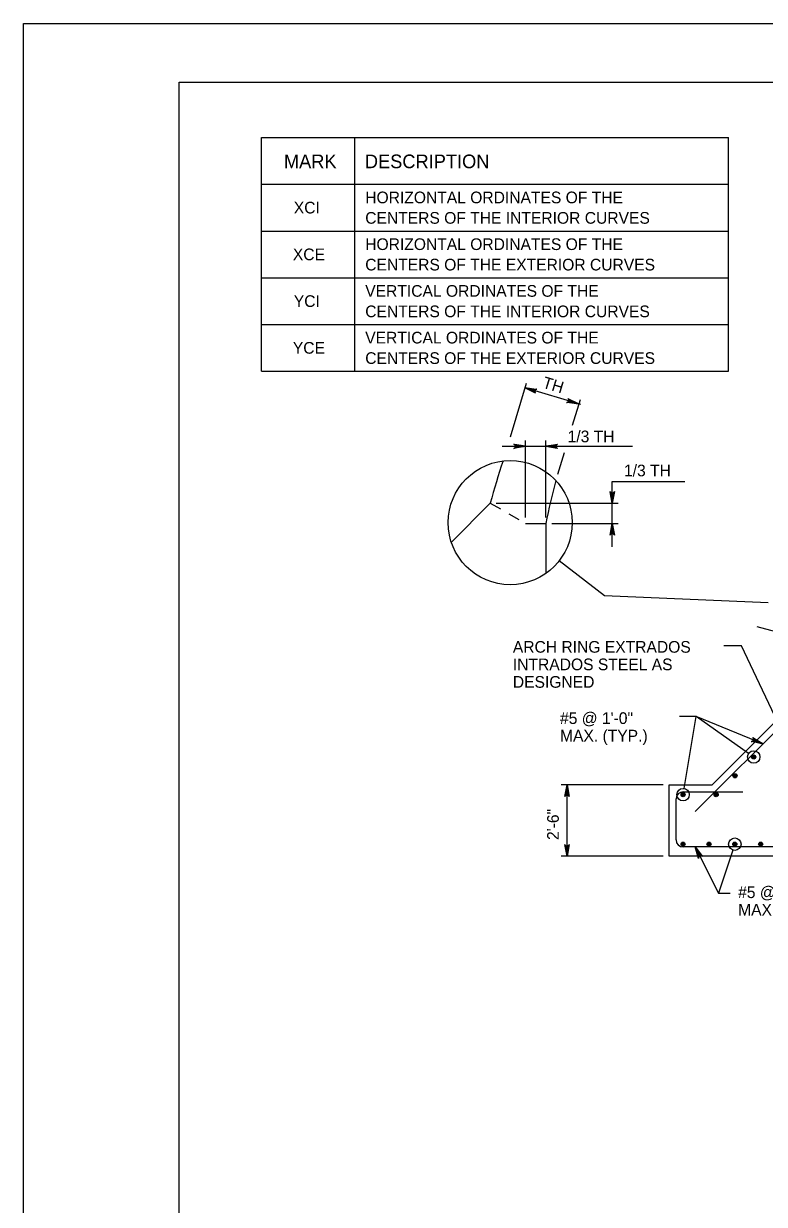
# Model space of a CAD drawing. Extents: x 639028 to 639883, y 298843 to 300031.
# Drawn here: x 639027.7 to 639218, y 299727.9 to 300031.1 of the extents above; entities that cross this region are included whole.
import ezdxf

# ---------------------------------------------------------------- set-up
doc = ezdxf.new("R2010")
doc.units = 0
for name, color, linetype in [('1', 7, 'Continuous'), ('2', 7, 'Continuous'), ('52', 7, 'Continuous'), ('PLT-BNDY', 7, 'Continuous')]:
    doc.layers.add(name, color=color, linetype=linetype)

# ---------------------------------------------------------------- blocks, each defined once
blk = doc.blocks.new('LT')
at = {"layer": '1'}
blk.add_lwpolyline([(0, 0), (-11.2, -2.1), (-10.8, -1.8), (-10.3, -1.5), (-10.1, -1.1), (-9.9, -0.8), (-9.8, -0.4), (-9.8, 0), (-9.8, 0.4), (-9.9, 0.8), (-10.1, 1.1), (-10.3, 1.5), (-10.8, 1.8), (-11.2, 2.1), (0, 0), (-10.8, 1.8), (-10.3, 1.5), (0, 0), (-10.1, 1.1), (-9.9, 0.8), (0, 0), (-9.8, 0.4), (-9.8, 0), (0, 0), (-9.8, -0.4), (-9.9, -0.8), (0, 0), (-10.1, -1.1), (-10.3, -1.5), (0, 0), (-10.8, -1.8)], dxfattribs=at)

msp = doc.modelspace()

# ---------------------------------------------------------------- linework, layer by layer
at = {"layer": '2'}
for p, q in [((639067.74, 299452.08), (639067.74, 300016.08)), ((639067.74, 300016.08), (639853.74, 300016.08)), ((639088.81, 299941.83), (639088.81, 300001.83)), ((639088.81, 300001.83), (639208.81, 300001.83)), ((639112.81, 299941.83), (639112.81, 300001.83)), ((639208.81, 299941.83), (639208.81, 300001.83)), ((639088.81, 299989.83), (639208.81, 299989.83)), ((639088.81, 299977.83), (639208.81, 299977.83)), ((639088.81, 299965.83), (639208.81, 299965.83)), ((639088.81, 299953.83), (639208.81, 299953.83)), ((639088.81, 299941.83), (639208.81, 299941.83)), ((639137.62, 299897.94), (639147.63, 299907.95)), ((639147.63, 299907.95), (639150.24, 299906.46)), ((639152.43, 299905.2), (639154.98, 299903.75)), ((639156.71, 299902.76), (639161.9, 299902.76)), ((639161.9, 299902.76), (639161.9, 299889.92)), ((639204.59, 299835.65), (639239.04, 299870.11)), ((639200.24, 299828.76), (639238.07, 299866.59)), ((639193.55, 299817.28), (639193.55, 299835.65)), ((639193.55, 299835.65), (639204.59, 299835.65)), ((639195.35, 299821.48), (639195.35, 299832.05)), ((639197.15, 299833.85), (639212.53, 299833.85)), ((639256.92, 299819.68), (639197.15, 299819.68)), ((639260.52, 299817.28), (639193.55, 299817.28))]:
    msp.add_line(p, q, dxfattribs=at)
for centre, radius in [((639215.3, 299842.8), 0.533), ((639215.3, 299842.8), 0.4), ((639215.3, 299842.8), 0.267), ((639215.3, 299842.8), 0.133), ((639210.47, 299837.96), 0.533), ((639210.47, 299837.96), 0.4), ((639210.47, 299837.96), 0.267), ((639210.47, 299837.96), 0.133), ((639197.15, 299833.13), 0.533), ((639197.15, 299833.13), 0.4), ((639197.15, 299833.13), 0.267), ((639197.15, 299833.13), 0.133), ((639205.63, 299833.13), 0.533), ((639205.63, 299833.13), 0.4), ((639205.63, 299833.13), 0.267), ((639205.63, 299833.13), 0.133), ((639197.15, 299820.4), 0.533), ((639197.15, 299820.4), 0.4), ((639197.15, 299820.4), 0.267), ((639197.15, 299820.4), 0.133), ((639203.79, 299820.4), 0.533), ((639203.79, 299820.4), 0.4), ((639203.79, 299820.4), 0.267), ((639203.79, 299820.4), 0.133), ((639210.43, 299820.4), 0.533), ((639210.43, 299820.4), 0.4), ((639210.43, 299820.4), 0.267), ((639210.43, 299820.4), 0.133), ((639217.07, 299820.4), 0.533), ((639217.07, 299820.4), 0.4), ((639217.07, 299820.4), 0.267), ((639217.07, 299820.4), 0.133)]:
    msp.add_circle(centre, radius, dxfattribs=at)
for centre, radius, start, end in [((639312.8, 299863.94), 170.93, 161.2841, 165.0802), ((639305.41, 299874.91), 146.18, 164.5943, 169.0167), ((639197.15, 299832.05), 1.8, 90, 180), ((639197.15, 299821.48), 1.8, 180, 270)]:
    msp.add_arc(centre, radius, start, end, dxfattribs=at)
at = {"layer": '52'}
for p, q in [((639152.78, 299925), (639156.94, 299938.74)), ((639170.86, 299933.27), (639156.59, 299937.59)), ((639168.77, 299927.95), (639170.77, 299934.56)), ((639156.71, 299904.26), (639156.71, 299924.06)), ((639161.9, 299904.26), (639161.9, 299924.06)), ((639150.71, 299922.56), (639184.16, 299922.56)), ((639164.99, 299915.43), (639166.67, 299921)), ((639178.94, 299896.76), (639178.94, 299913.48)), ((639178.94, 299913.48), (639197.61, 299913.48)), ((639149.13, 299907.95), (639180.44, 299907.95)), ((639163.4, 299902.76), (639180.44, 299902.76)), ((639235.8, 299870.97), (639216.19, 299876.2)), ((639215.3, 299842.8), (639215.3, 299842.8)), ((639192.05, 299835.65), (639165.84, 299835.65)), ((639167.34, 299817.28), (639167.34, 299835.65)), ((639197.15, 299833.13), (639197.15, 299833.13)), ((639210.43, 299820.4), (639210.43, 299820.4)), ((639192.05, 299817.28), (639165.84, 299817.28))]:
    msp.add_line(p, q, dxfattribs=at)
for points in [[(639156.59, 299937.59), (639159.6, 299937.26), (639159.47, 299937.22), (639159.34, 299937.17), (639159.25, 299937.1), (639159.17, 299937.02), (639159.12, 299936.93), (639159.08, 299936.84), (639159.06, 299936.73), (639159.05, 299936.63), (639159.08, 299936.52), (639159.11, 299936.41), (639159.19, 299936.3), (639159.28, 299936.19), (639156.59, 299937.59), (639159.19, 299936.3), (639159.11, 299936.41), (639156.59, 299937.59), (639159.08, 299936.52), (639159.05, 299936.63), (639156.59, 299937.59), (639159.06, 299936.73), (639159.08, 299936.84), (639156.59, 299937.59), (639159.12, 299936.93), (639159.17, 299937.02), (639156.59, 299937.59), (639159.25, 299937.1), (639159.34, 299937.17), (639156.59, 299937.59), (639159.47, 299937.22)], [(639170.25, 299933.46), (639167.23, 299933.79), (639167.37, 299933.83), (639167.5, 299933.87), (639167.59, 299933.95), (639167.67, 299934.03), (639167.72, 299934.12), (639167.76, 299934.21), (639167.78, 299934.31), (639167.79, 299934.41), (639167.76, 299934.52), (639167.73, 299934.64), (639167.65, 299934.75), (639167.56, 299934.86), (639170.25, 299933.46), (639167.65, 299934.75), (639167.73, 299934.64), (639170.25, 299933.46), (639167.76, 299934.52), (639167.79, 299934.41), (639170.25, 299933.46), (639167.78, 299934.31), (639167.76, 299934.21), (639170.25, 299933.46), (639167.72, 299934.12), (639167.67, 299934.03), (639170.25, 299933.46), (639167.59, 299933.95), (639167.5, 299933.87), (639170.25, 299933.46), (639167.37, 299933.83)], [(639165.35, 299893.21), (639176.98, 299884.23), (639218.99, 299882.45)], [(639248.28, 299847.09), (639223.79, 299846.75), (639212.15, 299871.31), (639207.6, 299871.31)], [(639217.61, 299846.13), (639200.54, 299853.17), (639196.26, 299853.17)], [(639197.42, 299834.71), (639200.54, 299853.17)], [(639213.99, 299843.72), (639200.54, 299853.17)], [(639217.61, 299846.13), (639214.64, 299846.75), (639214.78, 299846.78), (639214.92, 299846.81), (639215.01, 299846.88), (639215.1, 299846.95), (639215.16, 299847.03), (639215.21, 299847.12), (639215.23, 299847.22), (639215.25, 299847.32), (639215.24, 299847.43), (639215.22, 299847.55), (639215.14, 299847.66), (639215.07, 299847.78), (639217.61, 299846.13), (639215.14, 299847.66), (639215.22, 299847.55), (639217.61, 299846.13), (639215.24, 299847.43), (639215.25, 299847.32), (639217.61, 299846.13), (639215.23, 299847.22), (639215.21, 299847.12), (639217.61, 299846.13), (639215.16, 299847.03), (639215.1, 299846.95), (639217.61, 299846.13), (639215.01, 299846.88), (639214.92, 299846.81), (639217.61, 299846.13), (639214.78, 299846.78)], [(639200.29, 299819.68), (639206.27, 299807.84), (639209.26, 299807.84)], [(639200.29, 299819.68), (639202.13, 299817.27), (639202.01, 299817.33), (639201.89, 299817.4), (639201.77, 299817.41), (639201.65, 299817.41), (639201.56, 299817.38), (639201.46, 299817.36), (639201.38, 299817.29), (639201.3, 299817.23), (639201.23, 299817.14), (639201.17, 299817.04), (639201.15, 299816.9), (639201.13, 299816.76), (639200.29, 299819.68), (639201.15, 299816.9), (639201.17, 299817.04), (639200.29, 299819.68), (639201.23, 299817.14), (639201.3, 299817.23), (639200.29, 299819.68), (639201.38, 299817.29), (639201.46, 299817.36), (639200.29, 299819.68), (639201.56, 299817.38), (639201.65, 299817.41), (639200.29, 299819.68), (639201.77, 299817.41), (639201.89, 299817.4), (639200.29, 299819.68), (639202.01, 299817.33)], [(639209.93, 299818.88), (639206.27, 299807.84)]]:
    msp.add_lwpolyline(points, dxfattribs=at)
for centre, radius in [((639152.74, 299902.96), 15.94), ((639215.3, 299842.8), 1.6), ((639197.15, 299833.13), 1.6), ((639210.43, 299820.4), 1.6)]:
    msp.add_circle(centre, radius, dxfattribs=at)
at = {"layer": 'PLT-BNDY'}
msp.add_lwpolyline([(639027.74, 300031.08), (639868.74, 300031.08), (639868.74, 299437.08), (639027.74, 299437.08)], close=True, dxfattribs=at)

# ---------------------------------------------------------------- block references
at = {"layer": '52', "xscale": 0.2682193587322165, "yscale": 0.26822435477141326}
msp.add_blockref('LT', (639156.71, 299922.56), dxfattribs=at)
for p, rotation in [((639161.9, 299922.56), 180), ((639178.94, 299907.95), -90), ((639178.94, 299902.76), 90), ((639167.34, 299835.65), 90), ((639167.34, 299817.28), -90)]:
    msp.add_blockref('LT', p, dxfattribs=dict(at, rotation=rotation))

# ---------------------------------------------------------------- texts
at = {"layer": '2'}
for s, height, p in [('MARK', 3.5, (639094.61, 299993.96)), ('DESCRIPTION', 3.5, (639115.41, 299993.96)), ('HORIZONTAL ORDINATES OF THE', 3, (639115.5, 299984.95)), ('XCI', 3, (639097.15, 299982.33)), ('CENTERS OF THE INTERIOR CURVES', 3, (639115.5, 299979.7)), ('HORIZONTAL ORDINATES OF THE', 3, (639115.5, 299972.95)), ('XCE', 3, (639096.91, 299970.33)), ('CENTERS OF THE EXTERIOR CURVES', 3, (639115.5, 299967.7)), ('VERTICAL ORDINATES OF THE', 3, (639115.5, 299960.95)), ('YCI', 3, (639097.15, 299958.33)), ('CENTERS OF THE INTERIOR CURVES', 3, (639115.5, 299955.7)), ('VERTICAL ORDINATES OF THE', 3, (639115.5, 299948.95)), ('YCE', 3, (639096.91, 299946.33)), ('CENTERS OF THE EXTERIOR CURVES', 3, (639115.5, 299943.7)), ('1/3 TH', 3, (639167.49, 299923.59)), ('1/3 TH', 3, (639181.97, 299914.84)), ('ARCH RING EXTRADOS', 3, (639153.42, 299869.56)), ('INTRADOS STEEL AS', 3, (639153.42, 299865.06)), ('DESIGNED', 3, (639153.42, 299860.56)), ('#5 @ 1\'-0"', 3, (639165.54, 299851.26)), ('MAX. (TYP.)', 3, (639165.54, 299846.76)), ('#5 @ 1\'-0"', 3, (639211.29, 299806.57)), ('MAX. (TYP.)', 3, (639211.29, 299802.07))]:
    msp.add_text(s, height=height, dxfattribs=at).set_placement(p)
msp.add_text('TH', height=3, rotation=343.1823, dxfattribs=at).set_placement((639160.82, 299937.65))
at = {"layer": '52'}
msp.add_text('2\'-6"', height=3, rotation=90, dxfattribs=at).set_placement((639165.23, 299821.47))

doc.saveas('drawing.dxf')
